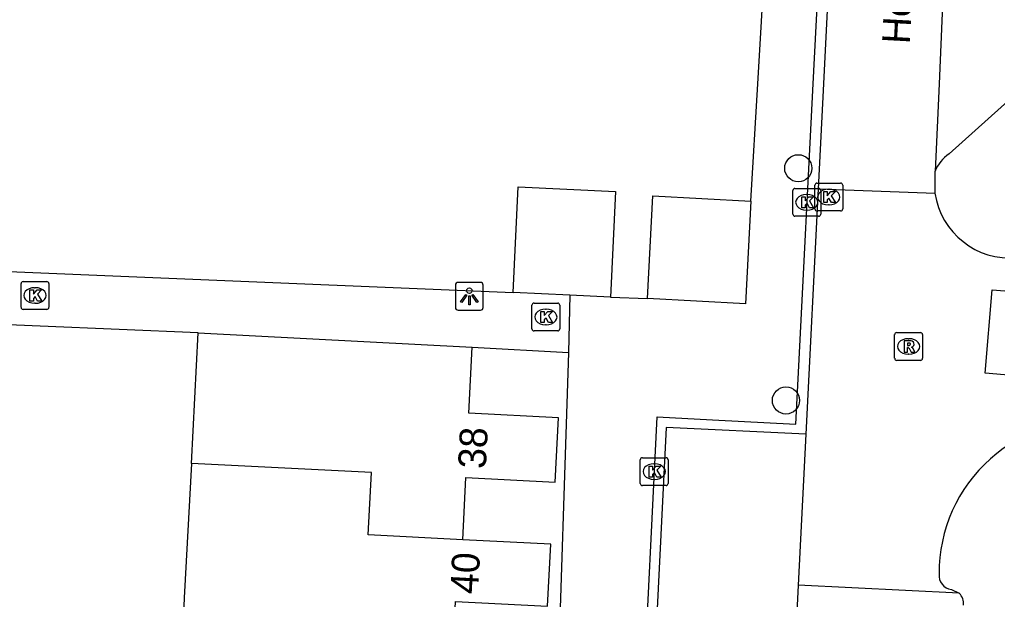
# Model space of a CAD drawing. Extents: x 162990 to 165007, y 383433 to 384336.
# Drawn here: x 164423.42 to 164458.56, y 383731.48 to 383752.31 of the extents above; entities that cross this region are included whole.
import ezdxf

# ---------------------------------------------------------------- set-up
doc = ezdxf.new("R2010")
doc.units = 0
for name, color, linetype in [('IMGEO_Boom', 7, 'Continuous'), ('IMGEO_Kolk', 7, 'Continuous'), ('IMGEO_Lichtpunt', 7, 'Continuous'), ('IMGEO_Muur', 7, 'Continuous'), ('IMGEO_Openbare_ruimte_label', 7, 'Continuous'), ('IMGEO_Pand', 7, 'Continuous'), ('IMGEO_Pand_nummerreeks', 7, 'Continuous'), ('IMGEO_Rijbaan_lokaal_open', 7, 'Continuous'), ('IMGEO_Rioolput', 7, 'Continuous'), ('IMGEO_Voetpad_open', 7, 'Continuous')]:
    doc.layers.add(name, color=color, linetype=linetype)

msp = doc.modelspace()

# ---------------------------------------------------------------- linework, layer by layer
at = {"layer": 'IMGEO_Boom'}
for centre in [(164451.404, 383746.97), (164450.961, 383738.63)]:
    msp.add_circle(centre, 0.489, dxfattribs=at)
at = {"layer": 'IMGEO_Kolk'}
for p, q in [((164452.074, 383746.436), (164452.926, 383746.436)), ((164451.209, 383745.321), (164451.209, 383746.173)), ((164451.284, 383746.247), (164452.136, 383746.247)), ((164451.999, 383745.51), (164451.999, 383746.362)), ((164452.21, 383746.173), (164452.21, 383745.321)), ((164452.487, 383746.216), (164452.512, 383746.216)), ((164453, 383746.362), (164453, 383745.51)), ((164451.697, 383746.027), (164451.722, 383746.027)), ((164451.72, 383745.467), (164451.695, 383745.467)), ((164452.926, 383745.436), (164452.074, 383745.436)), ((164452.51, 383745.656), (164452.485, 383745.656)), ((164452.136, 383745.247), (164451.284, 383745.247)), ((164423.471, 383741.974), (164423.471, 383742.826)), ((164423.546, 383742.9), (164424.398, 383742.9)), ((164423.959, 383742.68), (164423.984, 383742.68)), ((164424.472, 383742.826), (164424.472, 383741.974)), ((164424.398, 383741.9), (164423.546, 383741.9)), ((164423.982, 383742.12), (164423.957, 383742.12)), ((164441.831, 383741.2), (164441.831, 383742.052)), ((164441.906, 383742.126), (164442.758, 383742.126)), ((164442.319, 383741.906), (164442.344, 383741.906)), ((164442.832, 383742.052), (164442.832, 383741.2)), ((164442.342, 383741.346), (164442.317, 383741.346)), ((164442.758, 383741.126), (164441.906, 383741.126)), ((164445.726, 383735.646), (164445.726, 383736.498)), ((164445.801, 383736.572), (164446.653, 383736.572)), ((164446.214, 383736.352), (164446.239, 383736.352)), ((164446.727, 383736.498), (164446.727, 383735.646)), ((164446.653, 383735.572), (164445.801, 383735.572)), ((164446.237, 383735.792), (164446.212, 383735.792))]:
    msp.add_line(p, q, dxfattribs=at)
for points in [[(164452.074, 383746.436), (164452.926, 383746.436)], [(164451.209, 383745.321), (164451.209, 383746.173)], [(164451.284, 383746.247), (164452.136, 383746.247)], [(164451.999, 383745.51), (164451.999, 383746.362)], [(164452.21, 383746.173), (164452.21, 383745.321)], [(164452.32, 383746.136), (164452.443, 383746.136), (164452.443, 383745.985), (164452.573, 383746.136), (164452.737, 383746.136), (164452.591, 383745.985), (164452.744, 383745.736), (164452.592, 383745.736), (164452.507, 383745.9), (164452.443, 383745.833), (164452.443, 383745.736), (164452.32, 383745.736), (164452.32, 383746.136)], [(164453, 383746.362), (164453, 383745.51)], [(164451.53, 383745.947), (164451.653, 383745.947), (164451.653, 383745.796), (164451.783, 383745.947), (164451.947, 383745.947), (164451.801, 383745.796), (164451.954, 383745.547), (164451.802, 383745.547), (164451.717, 383745.711), (164451.653, 383745.644), (164451.653, 383745.547), (164451.53, 383745.547), (164451.53, 383745.947)], [(164452.926, 383745.436), (164452.074, 383745.436)], [(164452.136, 383745.247), (164451.284, 383745.247)], [(164423.471, 383741.974), (164423.471, 383742.826)], [(164423.546, 383742.9), (164424.398, 383742.9)], [(164423.792, 383742.6), (164423.915, 383742.6), (164423.915, 383742.449), (164424.045, 383742.6), (164424.209, 383742.6), (164424.063, 383742.449), (164424.216, 383742.2), (164424.064, 383742.2), (164423.979, 383742.364), (164423.915, 383742.297), (164423.915, 383742.2), (164423.792, 383742.2), (164423.792, 383742.6)], [(164424.472, 383742.826), (164424.472, 383741.974)], [(164424.398, 383741.9), (164423.546, 383741.9)], [(164441.831, 383741.2), (164441.831, 383742.052)], [(164441.906, 383742.126), (164442.758, 383742.126)], [(164442.832, 383742.052), (164442.832, 383741.2)], [(164442.152, 383741.826), (164442.275, 383741.826), (164442.275, 383741.675), (164442.405, 383741.826), (164442.569, 383741.826), (164442.423, 383741.675), (164442.576, 383741.426), (164442.424, 383741.426), (164442.339, 383741.59), (164442.275, 383741.523), (164442.275, 383741.426), (164442.152, 383741.426), (164442.152, 383741.826)], [(164442.758, 383741.126), (164441.906, 383741.126)], [(164445.726, 383735.646), (164445.726, 383736.498)], [(164445.801, 383736.572), (164446.653, 383736.572)], [(164446.047, 383736.272), (164446.17, 383736.272), (164446.17, 383736.121), (164446.3, 383736.272), (164446.464, 383736.272), (164446.318, 383736.121), (164446.471, 383735.872), (164446.319, 383735.872), (164446.234, 383736.036), (164446.17, 383735.969), (164446.17, 383735.872), (164446.047, 383735.872), (164446.047, 383736.272)], [(164446.727, 383736.498), (164446.727, 383735.646)], [(164446.653, 383735.572), (164445.801, 383735.572)]]:
    msp.add_lwpolyline(points, dxfattribs=at)
for centre, start, end in [((164452.076, 383746.36), 91.552, 178.448), ((164452.076, 383746.36), 91.552, 178.448), ((164452.924, 383746.36), 1.552, 88.448), ((164452.924, 383746.36), 1.552, 88.448), ((164451.286, 383746.171), 91.552, 178.448), ((164451.286, 383746.171), 91.552, 178.448), ((164452.134, 383746.171), 1.552, 88.448), ((164452.134, 383746.171), 1.552, 88.448), ((164452.076, 383745.512), 181.552, 268.448), ((164452.076, 383745.512), 181.552, 268.448), ((164452.924, 383745.512), 271.552, 358.448), ((164452.924, 383745.512), 271.552, 358.448), ((164451.286, 383745.323), 181.552, 268.448), ((164451.286, 383745.323), 181.552, 268.448), ((164452.134, 383745.323), 271.552, 358.448), ((164452.134, 383745.323), 271.552, 358.448), ((164423.548, 383742.824), 91.552, 178.448), ((164423.548, 383742.824), 91.552, 178.448), ((164424.396, 383742.824), 1.552, 88.448), ((164424.396, 383742.824), 1.552, 88.448), ((164423.548, 383741.976), 181.552, 268.448), ((164423.548, 383741.976), 181.552, 268.448), ((164424.396, 383741.976), 271.552, 358.448), ((164424.396, 383741.976), 271.552, 358.448), ((164441.908, 383742.05), 91.552, 178.448), ((164441.908, 383742.05), 91.552, 178.448), ((164442.756, 383742.05), 1.552, 88.448), ((164442.756, 383742.05), 1.552, 88.448), ((164441.908, 383741.202), 181.552, 268.448), ((164441.908, 383741.202), 181.552, 268.448), ((164442.756, 383741.202), 271.552, 358.448), ((164442.756, 383741.202), 271.552, 358.448), ((164445.803, 383736.496), 91.552, 178.448), ((164445.803, 383736.496), 91.552, 178.448), ((164446.651, 383736.496), 1.552, 88.448), ((164446.651, 383736.496), 1.552, 88.448), ((164445.803, 383735.648), 181.552, 268.448), ((164445.803, 383735.648), 181.552, 268.448), ((164446.651, 383735.648), 271.552, 358.448), ((164446.651, 383735.648), 271.552, 358.448)]:
    msp.add_arc(centre, 0.0765, start, end, dxfattribs=at)
for centre, major_axis, ratio, start_param, end_param in [((164452.486, 383745.936), (-0.387, 0.002), 0.722429, 4.712389, 7.853982), ((164452.511, 383745.936), (-0.39, 0.002), 0.717154, 1.570796, 4.712389), ((164451.696, 383745.747), (-0.387, 0.002), 0.722429, 4.712389, 7.853982), ((164451.721, 383745.747), (-0.39, 0.002), 0.717154, 1.570796, 4.712389), ((164423.958, 383742.4), (-0.387, 0.002), 0.722429, 4.712389, 7.853982), ((164423.983, 383742.4), (-0.39, 0.002), 0.717154, 1.570796, 4.712389), ((164442.318, 383741.626), (-0.387, 0.002), 0.722429, 4.712389, 7.853982), ((164442.343, 383741.626), (-0.39, 0.002), 0.717154, 1.570796, 4.712389), ((164446.213, 383736.072), (-0.387, 0.002), 0.722429, 4.712389, 7.853982), ((164446.238, 383736.072), (-0.39, 0.002), 0.717154, 1.570796, 4.712389)]:
    msp.add_ellipse(centre, major_axis=major_axis, ratio=ratio, start_param=start_param, end_param=end_param, dxfattribs=at)
at = {"layer": 'IMGEO_Lichtpunt'}
for p, q in [((164439.083, 383742.774), (164439.083, 383741.967)), ((164439.083, 383742.774), (164439.083, 383741.967)), ((164439.985, 383742.869), (164439.177, 383742.869)), ((164439.985, 383742.869), (164439.177, 383742.869)), ((164440.079, 383741.967), (164440.079, 383742.774)), ((164440.079, 383741.967), (164440.079, 383742.774)), ((164439.177, 383741.873), (164439.985, 383741.873)), ((164439.177, 383741.873), (164439.985, 383741.873))]:
    msp.add_line(p, q, dxfattribs=at)
for points in [[(164439.457, 383742.438), (164439.496, 383742.41), (164439.308, 383742.148), (164439.27, 383742.175), (164439.457, 383742.438)], [(164439.559, 383742.39), (164439.606, 383742.39), (164439.606, 383742.068), (164439.559, 383742.068), (164439.559, 383742.39)], [(164439.669, 383742.41), (164439.707, 383742.437), (164439.894, 383742.175), (164439.855, 383742.147), (164439.669, 383742.41)]]:
    msp.add_lwpolyline(points, dxfattribs=at)
msp.add_circle((164439.582, 383742.572), 0.0994, dxfattribs=at)
for centre, start, end in [((164439.177, 383742.774), 90, 180), ((164439.177, 383742.774), 90, 180), ((164439.985, 383742.774), 0, 90), ((164439.985, 383742.774), 0, 90), ((164439.177, 383741.967), 180, 270), ((164439.177, 383741.967), 180, 270), ((164439.985, 383741.967), 270, 0), ((164439.985, 383741.967), 270, 360)]:
    msp.add_arc(centre, 0.0946, start, end, dxfattribs=at)
at = {"layer": 'IMGEO_Muur'}
for points in [[(164448.304, 383707.855), (164448.207, 383705.364), (164447.887, 383705.375), (164448.047, 383709.634), (164444.948, 383709.752), (164445.705, 383725.181), (164445.823, 383727.577), (164446.336, 383738.034), (164448.318, 383737.931), (164451.313, 383737.776), (164451.421, 383739.875), (164451.942, 383750), (164452.677, 383764.285), (164453.018, 383764.265)], [(164453.018, 383764.265), (164452.659, 383756.974), (164452.307, 383750), (164452.117, 383746.236)], [(164452.117, 383746.236), (164451.672, 383737.418)], [(164451.672, 383737.418), (164446.656, 383737.662), (164445.289, 383710.181), (164448.389, 383710.03), (164448.372, 383709.592)]]:
    msp.add_lwpolyline(points, dxfattribs=at)
at = {"layer": 'IMGEO_Pand'}
for points in [[(164441.155, 383742.509), (164441.339, 383746.3), (164444.837, 383746.131), (164444.654, 383742.339)], [(164445.987, 383742.286), (164446.179, 383745.975), (164449.699, 383745.793)], [(164449.699, 383745.793), (164449.508, 383742.103), (164445.987, 383742.286)], [(164443.194, 383742.41), (164441.155, 383742.509)], [(164444.654, 383742.339), (164443.194, 383742.41)], [(164429.6, 383736.367), (164429.842, 383741.053)], [(164429.842, 383741.053), (164439.681, 383740.544)], [(164439.344, 383733.625), (164439.459, 383735.86), (164442.671, 383735.694), (164442.791, 383738.003), (164439.558, 383738.171), (164439.681, 383740.544)], [(164429.6, 383736.367), (164429.339, 383731.531), (164429.245, 383729.467), (164432.48, 383729.301)], [(164439.344, 383733.625), (164435.948, 383733.802), (164436.064, 383736.035), (164429.6, 383736.367)], [(164438.959, 383728.969), (164439.085, 383731.41), (164442.394, 383731.239), (164442.509, 383733.46), (164439.344, 383733.625)]]:
    msp.add_lwpolyline(points, dxfattribs=at)
at = {"layer": 'IMGEO_Rijbaan_lokaal_open'}
for points in [[(164457.488, 383774.081), (164456.472, 383750), (164456.32, 383746.862)], [(164456.317, 383746.081), (164456.32, 383746.862)], [(164452.117, 383746.236), (164456.317, 383746.081)], [(164461.166, 383739.346), (164458.122, 383739.603), (164458.368, 383742.603), (164461.379, 383742.368), (164461.166, 383739.346)], [(164451.672, 383737.418), (164451.402, 383731.991)], [(164451.402, 383731.991), (164450.284, 383709.525)], [(164457.189, 383731.703), (164451.402, 383731.991)], [(164456.905, 383731.837), (164457.189, 383731.703)]]:
    msp.add_lwpolyline(points, dxfattribs=at)
for centre, radius, start, end in [((164459.021, 383746.477), 2.733, 188.3271, 274.9878), ((164461.942, 383732.436), 5.476, 82.7735, 180.4), ((164456.968, 383732.339), 0.506, 173.2641, 262.8245), ((164456.833, 383731.337), 0.51, 352.9388, 45.8435)]:
    msp.add_arc(centre, radius, start, end, dxfattribs=at)
at = {"layer": 'IMGEO_Rioolput'}
for p, q in [((164454.867, 383740.142), (164454.867, 383740.994)), ((164454.942, 383741.068), (164455.794, 383741.068)), ((164455.355, 383740.848), (164455.38, 383740.848)), ((164455.868, 383740.994), (164455.868, 383740.142)), ((164455.378, 383740.288), (164455.353, 383740.288)), ((164455.794, 383740.068), (164454.942, 383740.068))]:
    msp.add_line(p, q, dxfattribs=at)
for points in [[(164454.867, 383740.142), (164454.867, 383740.994)], [(164454.942, 383741.068), (164455.794, 383741.068)], [(164455.868, 383740.994), (164455.868, 383740.142)], [(164455.456, 383740.766), (164455.204, 383740.768), (164455.204, 383740.368)], [(164455.204, 383740.368), (164455.328, 383740.368), (164455.328, 383740.53), (164455.339, 383740.53)], [(164455.382, 383740.687), (164455.328, 383740.687), (164455.328, 383740.606)], [(164455.328, 383740.606), (164455.38, 383740.606)], [(164455.386, 383740.501), (164455.457, 383740.368), (164455.597, 383740.368), (164455.532, 383740.494)], [(164455.794, 383740.068), (164454.942, 383740.068)]]:
    msp.add_lwpolyline(points, dxfattribs=at)
for centre, radius, start, end in [((164454.944, 383740.992), 0.0765, 91.552, 178.448), ((164454.944, 383740.992), 0.0765, 91.552, 178.448), ((164455.792, 383740.992), 0.0765, 1.552, 88.448), ((164455.792, 383740.992), 0.0765, 1.552, 88.448), ((164455.338, 383740.477), 0.0533, 26.0293, 88.6989), ((164455.364, 383740.795), 0.19, 274.7715, 282.9687), ((164455.388, 383740.591), 0.0964, 77.0061, 93.1865), ((164455.402, 383740.648), 0.0378, 276.6634, 79.6772), ((164455.455, 383740.656), 0.109, 350.3612, 89.416), ((164455.453, 383740.656), 0.112, 277.5842, 350.9817), ((164455.437, 383740.441), 0.108, 29.5134, 73.7905), ((164454.944, 383740.144), 0.0765, 181.552, 268.448), ((164454.944, 383740.144), 0.0765, 181.552, 268.448), ((164455.792, 383740.144), 0.0765, 271.552, 358.448), ((164455.792, 383740.144), 0.0765, 271.552, 358.448)]:
    msp.add_arc(centre, radius, start, end, dxfattribs=at)
for centre, major_axis, ratio, start_param, end_param in [((164455.354, 383740.568), (-0.387, 0.002), 0.722429, 4.712389, 7.853982), ((164455.379, 383740.568), (-0.39, 0.002), 0.717154, 1.570796, 4.712389)]:
    msp.add_ellipse(centre, major_axis=major_axis, ratio=ratio, start_param=start_param, end_param=end_param, dxfattribs=at)
at = {"layer": 'IMGEO_Voetpad_open'}
for points in [[(164449.699, 383745.793), (164449.947, 383750), (164450.213, 383754.502)], [(164456.822, 383747.488), (164459.632, 383750), (164460.122, 383750.438)], [(164415.529, 383743.571), (164441.155, 383742.509)], [(164443.194, 383742.41), (164443.14, 383740.354)], [(164444.654, 383742.339), (164445.987, 383742.286)], [(164429.842, 383741.053), (164421.31, 383741.415)], [(164439.681, 383740.544), (164443.14, 383740.354)], [(164443.14, 383740.354), (164442.73, 383727.485), (164442.153, 383716.5)]]:
    msp.add_lwpolyline(points, dxfattribs=at)
msp.add_arc((164457.549, 383746.391), 1.316, 123.5297, 159.0168, dxfattribs=at)

# ---------------------------------------------------------------- texts
at = {"layer": 'IMGEO_Openbare_ruimte_label'}
msp.add_text('Heerkensveld', height=1, rotation=86.9059, dxfattribs=at).set_placement((164455.41, 383751.42))
at = {"layer": 'IMGEO_Pand_nummerreeks'}
for s, rotation, p in [('38', 87.025, (164440.172, 383736.157)), ('40', 87.038, (164439.892, 383731.657))]:
    msp.add_text(s, height=1, rotation=rotation, dxfattribs=at).set_placement(p)

doc.saveas('drawing.dxf')
